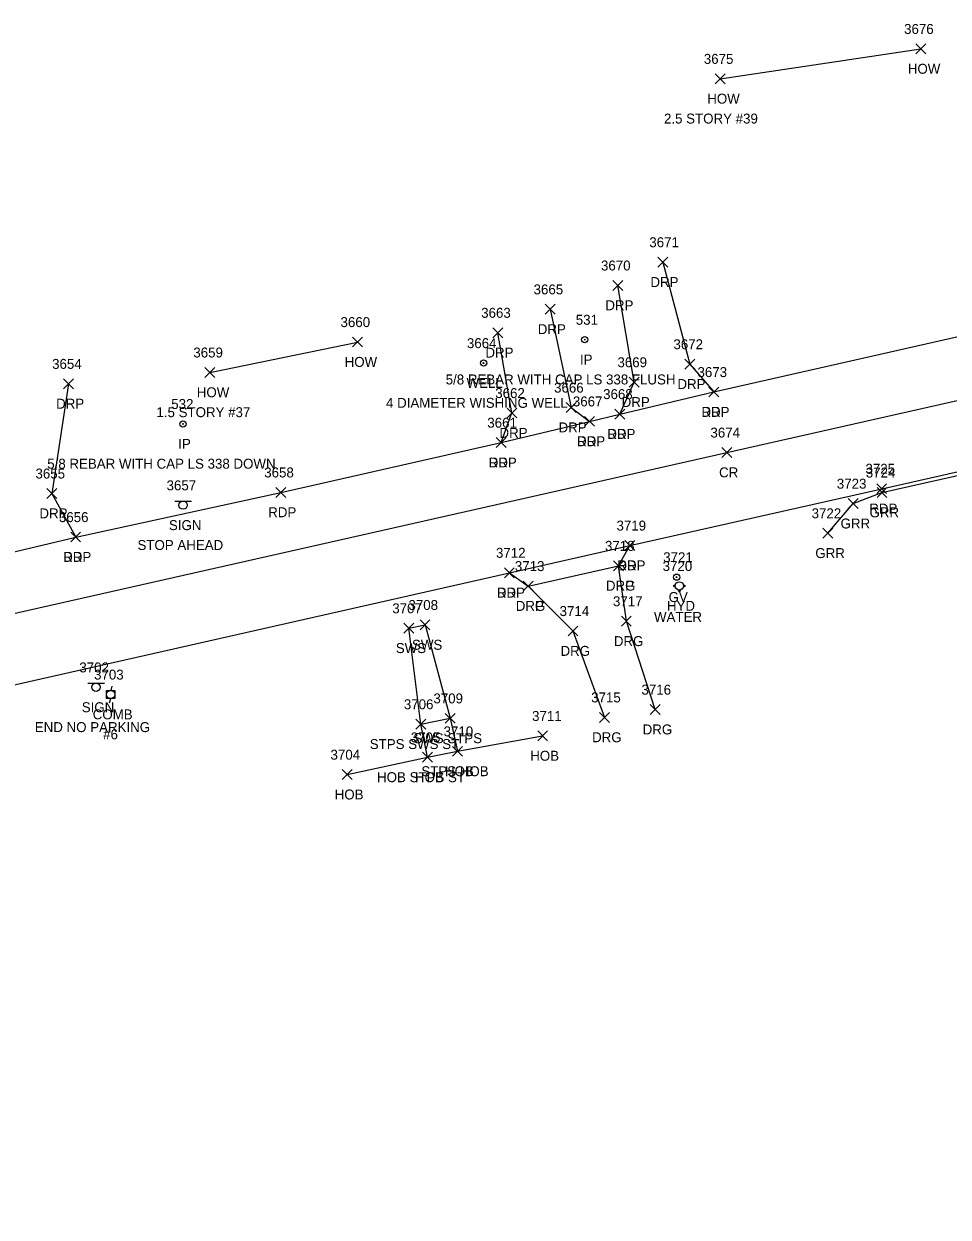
# Model space of a CAD drawing. Extents: x 1690689 to 1696275, y 438760 to 444007.
# Drawn here: x 1691672.4 to 1691858.3, y 442358.8 to 442598.7 of the extents above; entities that cross this region are included whole.
import ezdxf

# ---------------------------------------------------------------- set-up
doc = ezdxf.new("R2010")
doc.units = 0
for name, color, linetype in [('L_A', 7, 'Continuous'), ('L_C', 7, 'Continuous'), ('L_I', 7, 'Continuous'), ('L_TIC', 7, 'Continuous'), ('LBC', 7, 'Continuous'), ('LBF', 7, 'Continuous'), ('M_A', 7, 'Continuous'), ('M_C', 7, 'Continuous'), ('M_I', 7, 'Continuous'), ('MPIR', 7, 'Continuous'), ('P_A', 7, 'Continuous'), ('P_I', 7, 'Continuous'), ('P_TIC', 7, 'Continuous'), ('PET', 7, 'Continuous'), ('PRC', 7, 'Continuous'), ('R_A', 7, 'Continuous'), ('R_I', 7, 'Continuous'), ('R_TIC', 7, 'Continuous'), ('RDG', 7, 'Continuous'), ('RDP', 7, 'Continuous'), ('RGR', 7, 'Continuous'), ('RSW', 7, 'Continuous'), ('S_A', 7, 'Continuous'), ('S_C', 7, 'Continuous'), ('S_I', 7, 'Continuous'), ('SSGN', 7, 'Continuous'), ('U_A', 7, 'Continuous'), ('U_C', 7, 'Continuous'), ('U_I', 7, 'Continuous'), ('UP', 7, 'Continuous'), ('UWFH', 7, 'Continuous'), ('UWV', 7, 'Continuous'), ('UWW', 7, 'Continuous')]:
    doc.layers.add(name, color=color, linetype=linetype)

msp = doc.modelspace()

# ---------------------------------------------------------------- linework, layer by layer
at = {"layer": 'L_TIC'}
for points in [[(1691851.77, 442592.65), (1691853.77, 442594.65)], [(1691853.77, 442592.65), (1691851.77, 442594.65)], [(1691811.44, 442586.64), (1691813.44, 442588.64)], [(1691813.44, 442586.64), (1691811.44, 442588.64)], [(1691738.51, 442533.71), (1691740.51, 442535.71)], [(1691740.51, 442533.71), (1691738.51, 442535.71)], [(1691708.79, 442527.6), (1691710.79, 442529.6)], [(1691710.79, 442527.6), (1691708.79, 442529.6)], [(1691751.21, 442456.87), (1691753.21, 442458.87)], [(1691753.21, 442456.87), (1691751.21, 442458.87)], [(1691757.1, 442458.05), (1691759.1, 442460.05)], [(1691759.1, 442458.05), (1691757.1, 442460.05)], [(1691775.72, 442454.52), (1691777.72, 442456.52)], [(1691777.72, 442454.52), (1691775.72, 442456.52)], [(1691752.54, 442450.21), (1691754.54, 442452.21)], [(1691754.54, 442450.21), (1691752.54, 442452.21)], [(1691752.54, 442450.21), (1691754.54, 442452.21)], [(1691754.54, 442450.21), (1691752.54, 442452.21)], [(1691758.58, 442451.41), (1691760.58, 442453.41)], [(1691760.58, 442451.41), (1691758.58, 442453.41)], [(1691758.58, 442451.41), (1691760.58, 442453.41)], [(1691760.58, 442451.41), (1691758.58, 442453.41)], [(1691736.4, 442446.73), (1691738.4, 442448.73)], [(1691738.4, 442446.73), (1691736.4, 442448.73)]]:
    msp.add_lwpolyline(points, dxfattribs=at)
at = {"layer": 'LBC'}
for points in [[(1691812.44, 442587.64), (1691852.77, 442593.65)], [(1691709.79, 442528.6), (1691739.51, 442534.71)], [(1691737.4, 442447.73), (1691753.54, 442451.21), (1691759.58, 442452.41), (1691776.72, 442455.52)]]:
    msp.add_lwpolyline(points, dxfattribs=at)
at = {"layer": 'LBF'}
msp.add_lwpolyline([(1691753.54, 442451.21), (1691752.21, 442457.87), (1691758.1, 442459.05), (1691759.58, 442452.41)], dxfattribs=at)
at = {"layer": 'MPIR'}
for centre, radius in [((1691785.17, 442535.18), 0.625), ((1691785.17, 442535.18), 0.0833), ((1691704.39, 442518.24), 0.625), ((1691704.39, 442518.24), 0.0833)]:
    msp.add_circle(centre, radius, dxfattribs=at)
at = {"layer": 'P_TIC'}
for points in [[(1691810.17, 442523.66), (1691812.17, 442525.66)], [(1691812.17, 442523.66), (1691810.17, 442525.66)], [(1691791.23, 442519.23), (1691793.23, 442521.23)], [(1691793.23, 442519.23), (1691791.23, 442521.23)], [(1691785.16, 442517.76), (1691787.16, 442519.76)], [(1691787.16, 442517.76), (1691785.16, 442519.76)], [(1691767.38, 442513.48), (1691769.38, 442515.48)], [(1691769.38, 442513.48), (1691767.38, 442515.48)], [(1691812.76, 442511.5), (1691814.76, 442513.5)], [(1691814.76, 442511.5), (1691812.76, 442513.5)], [(1691723.04, 442503.48), (1691725.04, 442505.48)], [(1691725.04, 442503.48), (1691723.04, 442505.48)], [(1691843.9, 442504.22), (1691845.9, 442506.22)], [(1691845.9, 442504.22), (1691843.9, 442506.22)], [(1691681.81, 442494.5), (1691683.81, 442496.5)], [(1691683.81, 442494.5), (1691681.81, 442496.5)], [(1691793.27, 442492.8), (1691795.27, 442494.8)], [(1691795.27, 442492.8), (1691793.27, 442494.8)], [(1691769.02, 442487.32), (1691771.02, 442489.32)], [(1691771.02, 442487.32), (1691769.02, 442489.32)]]:
    msp.add_lwpolyline(points, dxfattribs=at)
at = {"layer": 'PET'}
for points in [[(1691244.99, 442422.42), (1691274.8, 442426.79), (1691288.71, 442428.52), (1691321.88, 442431.22), (1691333.08, 442431.36), (1691372.74, 442436.52), (1691410.43, 442441.3), (1691430.74, 442444.46), (1691471.26, 442451.19), (1691485.27, 442453.88), (1691572.21, 442470.9), (1691593.06, 442475.96), (1691664.16, 442491.04), (1691682.81, 442495.5), (1691724.04, 442504.48), (1691768.38, 442514.48), (1691786.16, 442518.76), (1691792.23, 442520.23), (1691811.17, 442524.66), (1691956.19, 442557.56), (1691977.69, 442562.36), (1692021.28, 442572.37)], [(1691262.71, 442389.79), (1691278.62, 442392.36), (1691323.95, 442400.43), (1691413.56, 442412.73), (1691416.45, 442413.87), (1691418.24, 442414.27), (1691431.74, 442416.27), (1691440.51, 442417.83), (1691444.91, 442417.31), (1691446.93, 442416.56), (1691480.01, 442421.07), (1691541.54, 442433.59), (1691592.5, 442446.57), (1691666.55, 442464.92), (1691770.02, 442488.32), (1691794.27, 442493.8), (1691844.9, 442505.22), (1691966.82, 442532.71), (1692001.23, 442540.45), (1692024.42, 442545.45)]]:
    msp.add_lwpolyline(points, dxfattribs=at)
at = {"layer": 'PRC'}
msp.add_lwpolyline([(1691130.81, 442358.75), (1691152.44, 442373.63), (1691178.23, 442388.18), (1691209.8, 442400.63), (1691248.04, 442408.48), (1691275.24, 442412.28), (1691309.15, 442415.93), (1691347.17, 442419.98), (1691395.19, 442425.91), (1691433.65, 442431.72), (1691478.76, 442438.88), (1691513.2, 442445.49), (1691566.06, 442456.6), (1691813.76, 442512.5), (1691980.06, 442550.02), (1692039.61, 442563.23)], dxfattribs=at)
at = {"layer": 'R_TIC'}
for points in [[(1691799.91, 442549.77), (1691801.91, 442551.77)], [(1691801.91, 442549.77), (1691799.91, 442551.77)], [(1691790.84, 442545.09), (1691792.84, 442547.09)], [(1691792.84, 442545.09), (1691790.84, 442547.09)], [(1691777.25, 442540.29), (1691779.25, 442542.29)], [(1691779.25, 442540.29), (1691777.25, 442542.29)], [(1691766.72, 442535.58), (1691768.72, 442537.58)], [(1691768.72, 442535.58), (1691766.72, 442537.58)], [(1691805.33, 442529.26), (1691807.33, 442531.26)], [(1691807.33, 442529.26), (1691805.33, 442531.26)], [(1691680.38, 442525.31), (1691682.38, 442527.31)], [(1691682.38, 442525.31), (1691680.38, 442527.31)], [(1691794.12, 442525.64), (1691796.12, 442527.64)], [(1691796.12, 442525.64), (1691794.12, 442527.64)], [(1691810.17, 442523.66), (1691812.17, 442525.66)], [(1691812.17, 442523.66), (1691810.17, 442525.66)], [(1691769.55, 442519.44), (1691771.55, 442521.44)], [(1691771.55, 442519.44), (1691769.55, 442521.44)], [(1691781.43, 442520.54), (1691783.43, 442522.54)], [(1691783.43, 442520.54), (1691781.43, 442522.54)], [(1691791.23, 442519.23), (1691793.23, 442521.23)], [(1691793.23, 442519.23), (1691791.23, 442521.23)], [(1691785.16, 442517.76), (1691787.16, 442519.76)], [(1691787.16, 442517.76), (1691785.16, 442519.76)], [(1691767.38, 442513.48), (1691769.38, 442515.48)], [(1691769.38, 442513.48), (1691767.38, 442515.48)], [(1691677.03, 442503.26), (1691679.03, 442505.26)], [(1691679.03, 442503.26), (1691677.03, 442505.26)], [(1691843.96, 442503.46), (1691845.96, 442505.46)], [(1691845.96, 442503.46), (1691843.96, 442505.46)], [(1691838.14, 442501.22), (1691840.14, 442503.22)], [(1691840.14, 442501.22), (1691838.14, 442503.22)], [(1691833.07, 442495.27), (1691835.07, 442497.27)], [(1691835.07, 442495.27), (1691833.07, 442497.27)], [(1691681.81, 442494.5), (1691683.81, 442496.5)], [(1691683.81, 442494.5), (1691681.81, 442496.5)], [(1691793.27, 442492.8), (1691795.27, 442494.8)], [(1691795.27, 442492.8), (1691793.27, 442494.8)], [(1691790.95, 442488.72), (1691792.95, 442490.72)], [(1691792.95, 442488.72), (1691790.95, 442490.72)], [(1691790.95, 442488.72), (1691792.95, 442490.72)], [(1691792.95, 442488.72), (1691790.95, 442490.72)], [(1691769.02, 442487.32), (1691771.02, 442489.32)], [(1691771.02, 442487.32), (1691769.02, 442489.32)], [(1691772.82, 442484.65), (1691774.82, 442486.65)], [(1691774.82, 442484.65), (1691772.82, 442486.65)], [(1691772.82, 442484.65), (1691774.82, 442486.65)], [(1691774.82, 442484.65), (1691772.82, 442486.65)], [(1691748.82, 442476.17), (1691750.82, 442478.17)], [(1691750.82, 442476.17), (1691748.82, 442478.17)], [(1691752.06, 442476.83), (1691754.06, 442478.83)], [(1691754.06, 442476.83), (1691752.06, 442478.83)], [(1691781.82, 442475.61), (1691783.82, 442477.61)], [(1691783.82, 442475.61), (1691781.82, 442477.61)], [(1691792.55, 442477.57), (1691794.55, 442479.57)], [(1691794.55, 442477.57), (1691792.55, 442479.57)], [(1691798.34, 442459.81), (1691800.34, 442461.81)], [(1691800.34, 442459.81), (1691798.34, 442461.81)], [(1691751.21, 442456.87), (1691753.21, 442458.87)], [(1691753.21, 442456.87), (1691751.21, 442458.87)], [(1691757.1, 442458.05), (1691759.1, 442460.05)], [(1691759.1, 442458.05), (1691757.1, 442460.05)], [(1691788.17, 442458.24), (1691790.17, 442460.24)], [(1691790.17, 442458.24), (1691788.17, 442460.24)]]:
    msp.add_lwpolyline(points, dxfattribs=at)
at = {"layer": 'RDG'}
for points in [[(1691799.34, 442460.81), (1691793.55, 442478.57), (1691791.95, 442489.72)], [(1691773.82, 442485.65), (1691782.82, 442476.61), (1691789.17, 442459.24)]]:
    msp.add_lwpolyline(points, dxfattribs=at)
at = {"layer": 'RDP'}
for points in [[(1691800.91, 442550.77), (1691806.33, 442530.26), (1691811.17, 442524.66)], [(1691792.23, 442520.23), (1691795.12, 442526.64), (1691791.84, 442546.09)], [(1691778.25, 442541.29), (1691782.43, 442521.54), (1691786.16, 442518.76)], [(1691768.38, 442514.48), (1691770.55, 442520.44), (1691767.72, 442536.58)], [(1691681.38, 442526.31), (1691678.03, 442504.26), (1691682.81, 442495.5)], [(1691770.02, 442488.32), (1691773.82, 442485.65), (1691791.95, 442489.72), (1691794.27, 442493.8)]]:
    msp.add_lwpolyline(points, dxfattribs=at)
at = {"layer": 'RGR'}
msp.add_lwpolyline([(1691834.07, 442496.27), (1691839.14, 442502.22), (1691844.96, 442504.46), (1691966.94, 442531.88), (1691975.95, 442531.42), (1691979.34, 442529.75)], dxfattribs=at)
at = {"layer": 'RSW'}
msp.add_lwpolyline([(1691752.21, 442457.87), (1691749.82, 442477.17), (1691753.06, 442477.83), (1691758.1, 442459.05)], dxfattribs=at)
at = {"layer": 'SSGN'}
for p, q in [((1691702.77, 442502.74), (1691706.11, 442502.74)), ((1691704.42, 442501.91), (1691704.42, 442501.91)), ((1691685.26, 442466.13), (1691688.59, 442466.13)), ((1691686.9, 442465.3), (1691686.9, 442465.3))]:
    msp.add_line(p, q, dxfattribs=at)
for centre in [(1691704.42, 442501.91), (1691686.9, 442465.3)]:
    msp.add_circle(centre, 0.833, dxfattribs=at)
at = {"layer": 'UP'}
for p, q in [((1691689.02, 442463.01), (1691689.02, 442464.67)), ((1691689.02, 442464.67), (1691690.68, 442464.67)), ((1691690.1, 442465.51), (1691689.85, 442464.67)), ((1691689.85, 442463.84), (1691689.85, 442463.84)), ((1691690.68, 442464.67), (1691690.68, 442463.01)), ((1691690.68, 442463.01), (1691689.02, 442463.01)), ((1691689.6, 442462.17), (1691689.85, 442463.01))]:
    msp.add_line(p, q, dxfattribs=at)
msp.add_circle((1691689.85, 442463.84), 0.833, dxfattribs=at)
at = {"layer": 'UWFH'}
msp.add_line((1691804.2, 442485.67), (1691804.2, 442485.67), dxfattribs=at)
for centre, radius in [((1691803.2, 442485.67), 0.167), ((1691804.2, 442485.67), 0.833), ((1691804.2, 442484.67), 0.167), ((1691805.2, 442485.67), 0.167)]:
    msp.add_circle(centre, radius, dxfattribs=at)
at = {"layer": 'UWV'}
for radius in [0.625, 0.0833]:
    msp.add_circle((1691803.65, 442487.43), radius, dxfattribs=at)
at = {"layer": 'UWW'}
for radius in [0.625, 0.0833]:
    msp.add_circle((1691764.84, 442530.48), radius, dxfattribs=at)

# ---------------------------------------------------------------- texts
at = {"layer": 'L_A'}
for s, p in [('HOW', (1691850.16, 442588.65)), ('HOW', (1691809.82, 442582.64)), ('HOW', (1691736.9, 442529.71)), ('HOW', (1691707.17, 442523.6)), ('SWS STPS', (1691750.71, 442454.05)), ('STPS SWS ST', (1691741.95, 442452.87)), ('HOB', (1691774.22, 442450.52)), ('STPS HOB', (1691752.33, 442447.41)), ('HOB', (1691757.08, 442447.41)), ('HOB STPS ST', (1691743.42, 442446.21)), ('HOB', (1691751.04, 442446.21)), ('HOB', (1691734.9, 442442.73))]:
    msp.add_text(s, height=2, dxfattribs=at).set_placement(p)
at = {"layer": 'L_C'}
for s, p in [('2.5 STORY #39', (1691801.12, 442578.64)), ('1.5 STORY #37', (1691699.05, 442519.6))]:
    msp.add_text(s, height=2, dxfattribs=at).set_placement(p)
at = {"layer": 'L_I'}
for s, p in [('3676', (1691849.41, 442596.65)), ('3675', (1691809.13, 442590.64)), ('3660', (1691736.07, 442537.71)), ('3659', (1691706.47, 442531.6)), ('3709', (1691754.75, 442462.05)), ('3706', (1691748.81, 442460.87)), ('3711', (1691774.59, 442458.52)), ('3705', (1691750.2, 442454.21)), ('3705', (1691750.2, 442454.21)), ('3710', (1691756.8, 442455.41)), ('3710', (1691756.8, 442455.41)), ('3704', (1691734.06, 442450.73))]:
    msp.add_text(s, height=2, dxfattribs=at).set_placement(p)
at = {"layer": 'M_A'}
for p in [(1691784.22, 442530.18), (1691703.44, 442513.24)]:
    msp.add_text('IP', height=2, dxfattribs=at).set_placement(p)
at = {"layer": 'M_C'}
for s, p in [('5/8 REBAR WITH CAP LS 338 FLUSH', (1691757.22, 442526.18)), ('5/8 REBAR WITH CAP LS 338 DOWN', (1691677.09, 442509.24))]:
    msp.add_text(s, height=2, dxfattribs=at).set_placement(p)
at = {"layer": 'M_I'}
for s, p in [('531', (1691783.38, 442538.18)), ('532', (1691702.03, 442521.24))]:
    msp.add_text(s, height=2, dxfattribs=at).set_placement(p)
at = {"layer": 'P_A'}
for s, p in [('RDP', (1691808.65, 442519.66)), ('RDP', (1691789.72, 442515.23)), ('RDP', (1691783.64, 442513.76)), ('RDP', (1691765.87, 442509.48)), ('CR', (1691812.2, 442507.5)), ('RDP', (1691842.39, 442500.22)), ('RDP', (1691721.53, 442499.48)), ('RDP', (1691680.3, 442490.5)), ('RDP', (1691791.75, 442488.8)), ('RDP', (1691767.51, 442483.32))]:
    msp.add_text(s, height=2, dxfattribs=at).set_placement(p)
at = {"layer": 'P_I'}
for s, p in [('3673', (1691807.86, 442527.66)), ('3667', (1691782.8, 442521.76)), ('3668', (1691788.88, 442523.23)), ('3661', (1691765.59, 442517.48)), ('3674', (1691810.46, 442515.5)), ('3658', (1691720.73, 442507.48)), ('3725', (1691841.64, 442508.22)), ('3656', (1691679.44, 442498.5)), ('3719', (1691791.57, 442496.8)), ('3712', (1691767.33, 442491.32))]:
    msp.add_text(s, height=2, dxfattribs=at).set_placement(p)
at = {"layer": 'R_A'}
for s, p in [('DRP', (1691798.39, 442545.77)), ('DRP', (1691789.33, 442541.09)), ('DRP', (1691775.74, 442536.29)), ('DRP', (1691765.21, 442531.58)), ('DRP', (1691803.82, 442525.26)), ('DRP', (1691678.87, 442521.31)), ('DRP', (1691792.61, 442521.64)), ('DRP', (1691808.65, 442519.66)), ('DRP', (1691779.92, 442516.54)), ('DRP', (1691768.04, 442515.44)), ('DRP', (1691789.72, 442515.23)), ('DRP', (1691783.64, 442513.76)), ('DRP', (1691765.87, 442509.48)), ('DRP', (1691675.52, 442499.26)), ('GRR', (1691836.63, 442497.22)), ('GRR', (1691842.45, 442499.46)), ('DRP', (1691680.3, 442490.5)), ('GRR', (1691831.55, 442491.27)), ('DRP', (1691791.75, 442488.8)), ('DRP', (1691767.51, 442483.32)), ('DRG', (1691789.44, 442484.72)), ('DRP', (1691789.44, 442484.72)), ('DRG', (1691771.31, 442480.65)), ('DRP', (1691771.31, 442480.65)), ('DRG', (1691791.04, 442473.57)), ('SWS', (1691747.19, 442472.17)), ('SWS', (1691750.44, 442472.83)), ('DRG', (1691780.31, 442471.61)), ('SWS STPS', (1691750.71, 442454.05)), ('DRG', (1691786.66, 442454.24)), ('DRG', (1691796.83, 442455.81)), ('STPS SWS ST', (1691741.95, 442452.87))]:
    msp.add_text(s, height=2, dxfattribs=at).set_placement(p)
at = {"layer": 'R_I'}
for s, p in [('3671', (1691798.17, 442553.77)), ('3670', (1691788.45, 442549.09)), ('3665', (1691774.9, 442544.29)), ('3663', (1691764.36, 442539.58)), ('3672', (1691803.02, 442533.26)), ('3654', (1691678.07, 442529.31)), ('3669', (1691791.76, 442529.64)), ('3673', (1691807.86, 442527.66)), ('3666', (1691779.02, 442524.54)), ('3662', (1691767.19, 442523.44)), ('3667', (1691782.8, 442521.76)), ('3668', (1691788.88, 442523.23)), ('3661', (1691765.59, 442517.48)), ('3655', (1691674.72, 442507.26)), ('3724', (1691841.7, 442507.46)), ('3723', (1691835.88, 442505.22)), ('3656', (1691679.44, 442498.5)), ('3722', (1691830.81, 442499.27)), ('3719', (1691791.57, 442496.8)), ('3718', (1691789.26, 442492.72)), ('3718', (1691789.26, 442492.72)), ('3712', (1691767.33, 442491.32)), ('3713', (1691771.13, 442488.65)), ('3713', (1691771.13, 442488.65)), ('3708', (1691749.73, 442480.83)), ('3717', (1691790.86, 442481.57)), ('3707', (1691746.48, 442480.17)), ('3714', (1691780.13, 442479.61)), ('3716', (1691796.59, 442463.81)), ('3709', (1691754.75, 442462.05)), ('3715', (1691786.48, 442462.24)), ('3706', (1691748.81, 442460.87))]:
    msp.add_text(s, height=2, dxfattribs=at).set_placement(p)
at = {"layer": 'S_A'}
for p in [(1691701.56, 442496.89), (1691684.04, 442460.28)]:
    msp.add_text('SIGN', height=2, dxfattribs=at).set_placement(p)
at = {"layer": 'S_C'}
for s, p in [('STOP AHEAD', (1691695.24, 442492.89)), ('END NO PARKING', (1691674.59, 442456.28))]:
    msp.add_text(s, height=2, dxfattribs=at).set_placement(p)
at = {"layer": 'S_I'}
for s, p in [('3657', (1691701.09, 442504.89)), ('3702', (1691683.55, 442468.28))]:
    msp.add_text(s, height=2, dxfattribs=at).set_placement(p)
at = {"layer": 'U_A'}
for s, p in [('WELL', (1691761.41, 442525.48)), ('HYD', (1691801.72, 442480.67)), ('GV', (1691802.05, 442482.43)), ('COMB', (1691686.24, 442458.84))]:
    msp.add_text(s, height=2, dxfattribs=at).set_placement(p)
at = {"layer": 'U_C'}
for s, p in [('4 DIAMETER WISHING WELL', (1691745.22, 442521.48)), ('WATER', (1691799.11, 442478.43)), ('#6', (1691688.33, 442454.84))]:
    msp.add_text(s, height=2, dxfattribs=at).set_placement(p)
at = {"layer": 'U_I'}
for s, p in [('3664', (1691761.49, 442533.48)), ('3721', (1691800.96, 442490.43)), ('3720', (1691800.85, 442488.67)), ('3703', (1691686.51, 442466.84))]:
    msp.add_text(s, height=2, dxfattribs=at).set_placement(p)

doc.saveas('drawing.dxf')
